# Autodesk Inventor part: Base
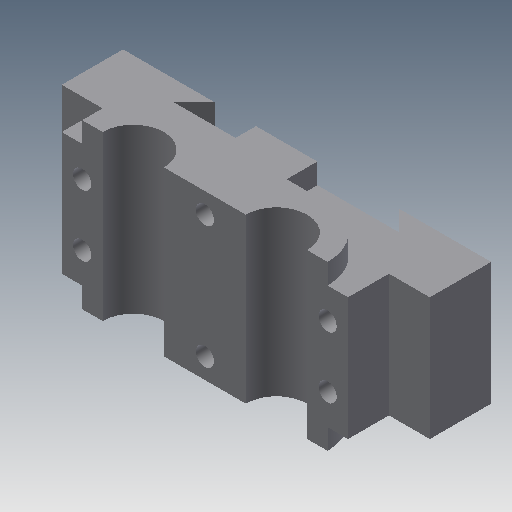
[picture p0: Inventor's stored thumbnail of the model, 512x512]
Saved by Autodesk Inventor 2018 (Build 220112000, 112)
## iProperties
Shininess: 77.0
Length Units: 11269
Angle Units: 11279
Time Units: 11290
Mass Units: 11283
Length Display Precision: 3
Angle Display Precision: 2
Created: 2002-02
Part Number: Base
Document SubType Name: Modeling
Designer: ***
Density: 1 g/cm^3
Material: Generic
Appearance: Default
Density: 0.0
Volumn: 0.0
Area: 0.0
PropertySet Name: Model Information
Control State: 0
Master: False
Checked Out: False
Author: ***
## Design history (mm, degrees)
sketch "Sketch2"
  geometry: L1 (-10.066, -1.263)-(24.934, -1.263); L2 (37.434, 11.237)-(32.434, 11.237); L3 (17.434, 11.237)-(-2.566, 11.237); L4 (-17.566, 11.237)-(-22.566, 11.237); A1 r 12.5 centre (-10.066, 11.237) between (-22.566, 11.237) and (-10.066, -1.263); A2 r 12.5 centre (24.934, 11.237) between (24.934, -1.263) and (37.434, 11.237); A3 r 7.5 centre (24.934, 11.237) between (17.434, 11.237) and (32.434, 11.237); A4 r 7.5 centre (-10.066, 11.237) between (-17.566, 11.237) and (-2.566, 11.237)
  constraints: 8 end point, 8 point on circle, 4 centre point, 3 horizontal, 3 parallel, 2 coincident, 2 equal radius, 2 tangent
  dimensions: "d0" = 12.5 radius of A1; "d1" = 7.5 radius of A4; "d2" = 35 distance of A1.centre A2.centre; "d3" = 12.5 distance between parallel lines of L3 L1
extrude "Extrusion1" new body sketch "Sketch2" stored distance "d4" = 40; taper "d5" = 0 deg
sketch "Sketch4"
  geometry: L1 (-27.566, 1.237)-(-37.566, 1.237); L2 (-37.566, 1.237)-(-37.566, -13.763); L3 (-37.566, -13.763)-(-15.066, -13.763); L4 (-15.066, -13.763)-(-20.066, -8.763); L5 (-20.066, -8.763)-(34.934, -8.763); L6 (34.934, -8.763)-(29.934, -13.763); L7 (29.934, -13.763)-(52.434, -13.763); L8 (52.434, -13.763)-(52.434, 1.237); L9 (52.434, 1.237)-(42.434, 1.237); L10 (24.934, -1.263)-(-10.066, -1.263); L11 (-17.566, 11.237)-(-22.566, 11.237) reference; L12 (37.434, 11.237)-(32.434, 11.237) reference; L13 (-22.566, 11.237)-(-27.566, 11.237); L14 (-27.566, 11.237)-(-27.566, 1.237); L15 (37.434, 11.237)-(42.434, 11.237); L16 (42.434, 11.237)-(42.434, 1.237); A1 r 12.5 centre (24.934, 11.237) between (24.934, -1.263) and (37.434, 11.237); A2 r 12.5 centre (-10.066, 11.237) between (-22.566, 11.237) and (-10.066, -1.263); A3 r 12.5 centre (24.934, 11.237) between (24.934, -1.263) and (37.434, 11.237) reference; A4 r 12.5 centre (-10.066, 11.237) between (-22.566, 11.237) and (-10.066, -1.263) reference
  constraints: 28 end point, 6 perpendicular, 5 equal length, 4 concentric, 4 parallel, 4 point on circle, 2 centre point, 2 collinear, 1 tangent
  dimensions: "d12" = 15 distance of L1.end L2.end; "d13" = 25 distance from line of L3 L11.end; "d14" = 90 distance between parallel lines of L2 L8; "d15" = 5 distance between parallel lines of L5 L7; "d16" = 22.5 distance of L2.end L3.end; "d24" = 5 distance of L12.start L15.end; "d25" = 15 distance from line of L8 L12.start
extrude "Extrusion3" join sketch "Sketch4" stored distance "d17" = 30; taper "d18" = 0 deg
sketch "Sketch5"
  geometry: L1 (-14.934, -1.263)-(0.066, -1.263); L2 (0.066, -1.263)-(0.066, -8.763); L3 (0.066, -8.763)-(-14.934, -8.763); L4 (-14.934, -8.763)-(-14.934, -1.263); L5 (10.066, -1.263)-(-24.934, -1.263) reference; 1 further point
  constraints: 8 end point, 2 parallel, 1 collinear, 1 horizontal, 1 perpendicular
  dimensions: "d19" = 7.5 distance of L1.end L2.end; "d20" = 15 distance of L2.end L3.end; "d21" = 15 distance from line of point (-29.934, -13.763) L4
extrude "Extrusion4" join sketch "Sketch5" distance "d22" = 40; taper "d23" = 0 deg
sketch "Sketch6"
  geometry: L1 (-5, -35)-(0, -35) reference; L2 (-5, -35)-(-5, -5) reference; 1 further point
  dimensions: "d26" = 7.5 distance from line of L1 point (0, -27.5); "d27" = 5 distance from line of L2 point (0, -27.5)
hole "Hole1" sketch "Sketch6" at (0, -27.5) diameter "d28" = 4.5; stored, may be unused: countersink angle "d32" = 82 deg, drill point angle "d34" = 0 deg; dims "d29" = 6, "d30" = 4, "d31" = 2, "d33" = 15
pattern_linear "Rectangular Pattern1" dims "d37" = 60, "d40" = 15
sketch "Sketch7"
  geometry: L1 (-20, -40)-(-20, -35) reference; L2 (0, -40)-(20, -40) reference; 1 further point
  dimensions: "d41" = 30 distance from line of L1 point (10, -35); "d42" = 5 distance from line of L2 point (10, -35)
hole "Hole2" sketch "Sketch7" at (10, -35) diameter "d43" = 4.5; stored, may be unused: countersink angle "d47" = 82 deg, drill point angle "d49" = 0 deg; dims "d44" = 6, "d45" = 4, "d46" = 2, "d48" = 15
pattern_linear "Rectangular Pattern2" dims "d52" = 30
body "Solid1"
